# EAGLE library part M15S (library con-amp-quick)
AMP QUICK CONNECTOR
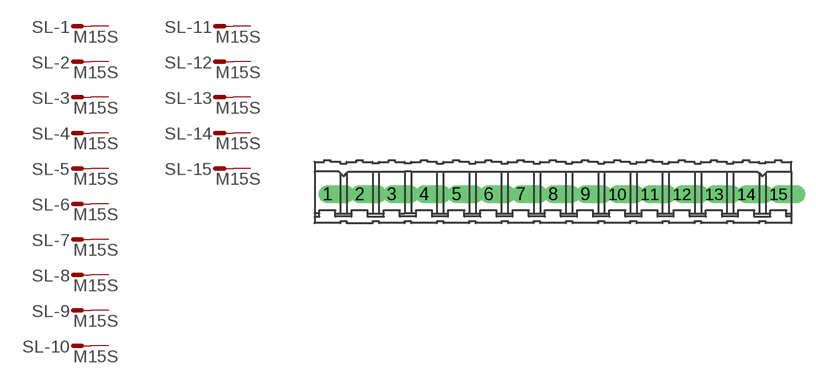
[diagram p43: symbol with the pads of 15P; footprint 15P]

Designator prefix SL; gates -1=M -2=M -3=M -4=M -5=M -6=M -7=M -8=M -9=M -10=M -11=M -12=M -13=M -14=M -15=M

## M15S  [15P]
1  -1:S  pas
2  -2:S  pas
3  -3:S  pas
4  -4:S  pas
5  -5:S  pas
6  -6:S  pas
7  -7:S  pas
8  -8:S  pas
9  -9:S  pas
10  -10:S  pas
11  -11:S  pas
12  -12:S  pas
13  -13:S  pas
14  -14:S  pas
15  -15:S  pas

## Footprint 15P (pad centres in mm)
AMP QUICK CONNECTOR
drill 0.914 offset: 1 -17.78,0; 2 -15.24,0; 3 -12.7,0; 4 -10.16,0; 5 -7.62,0; 6 -5.08,0; 7 -2.54,0; 8 0,0; 9 2.54,0; 10 5.08,0; 11 7.62,0; 12 10.16,0; 13 12.7,0; 14 15.24,0; 15 17.78,0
